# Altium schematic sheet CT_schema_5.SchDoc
size 430 x 429 mm
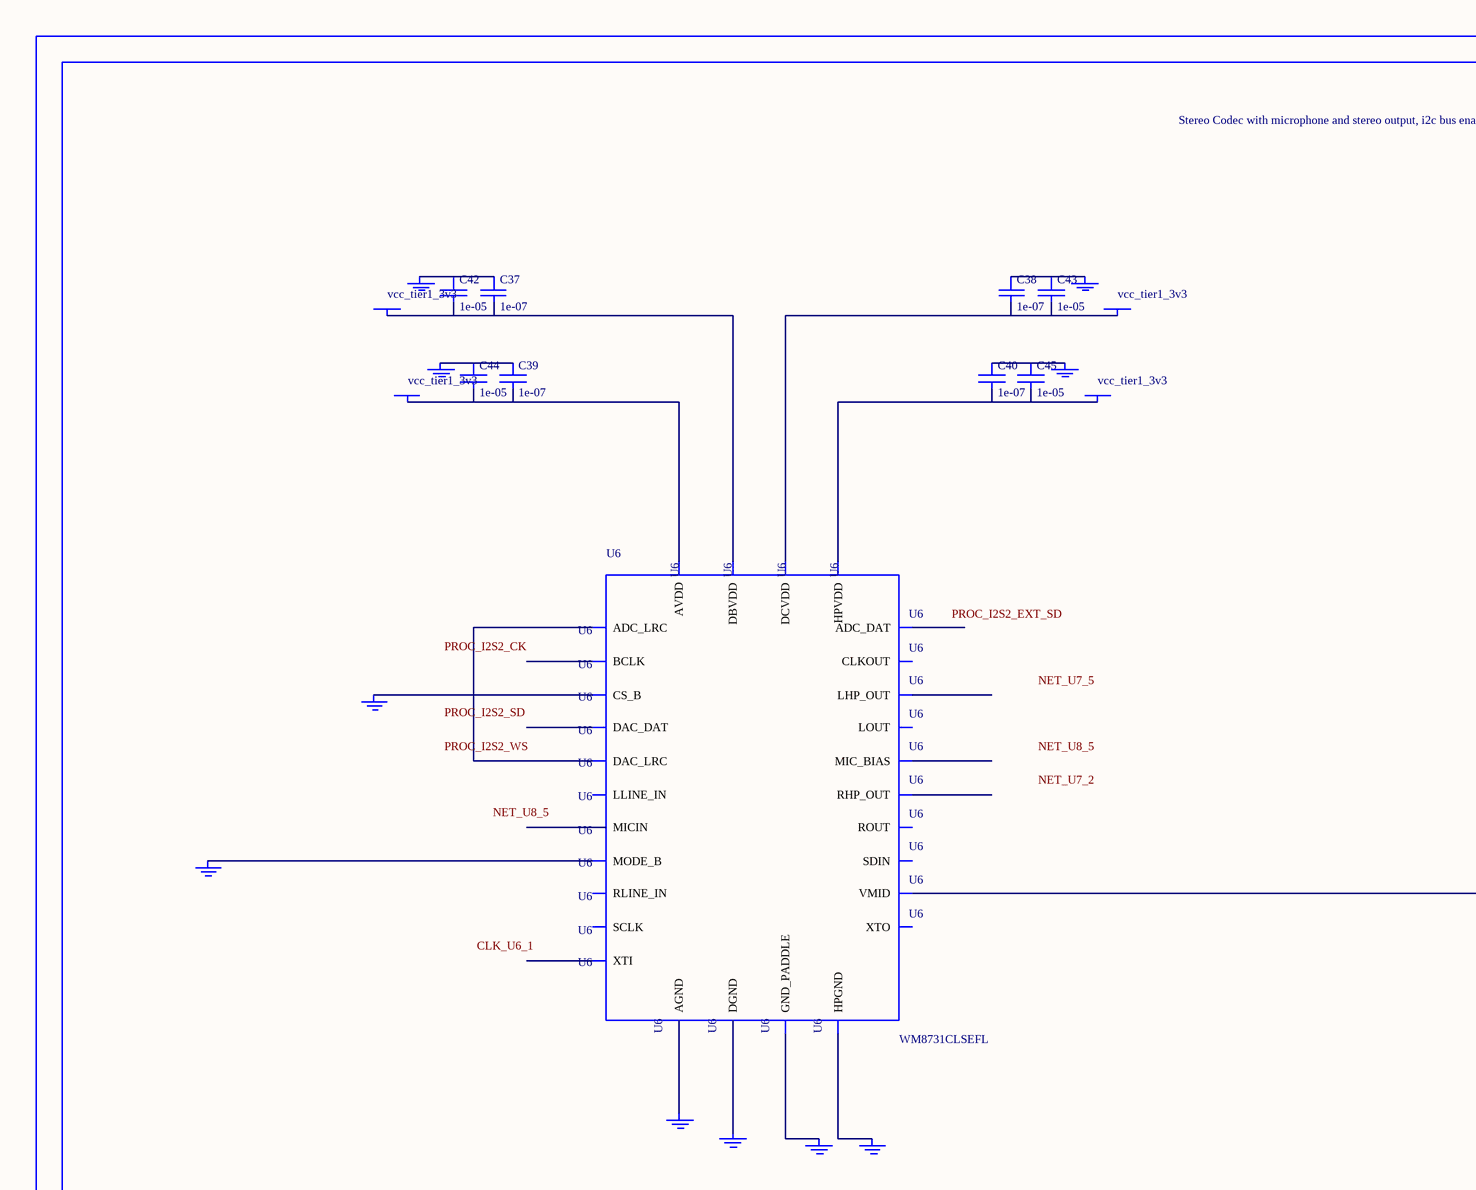
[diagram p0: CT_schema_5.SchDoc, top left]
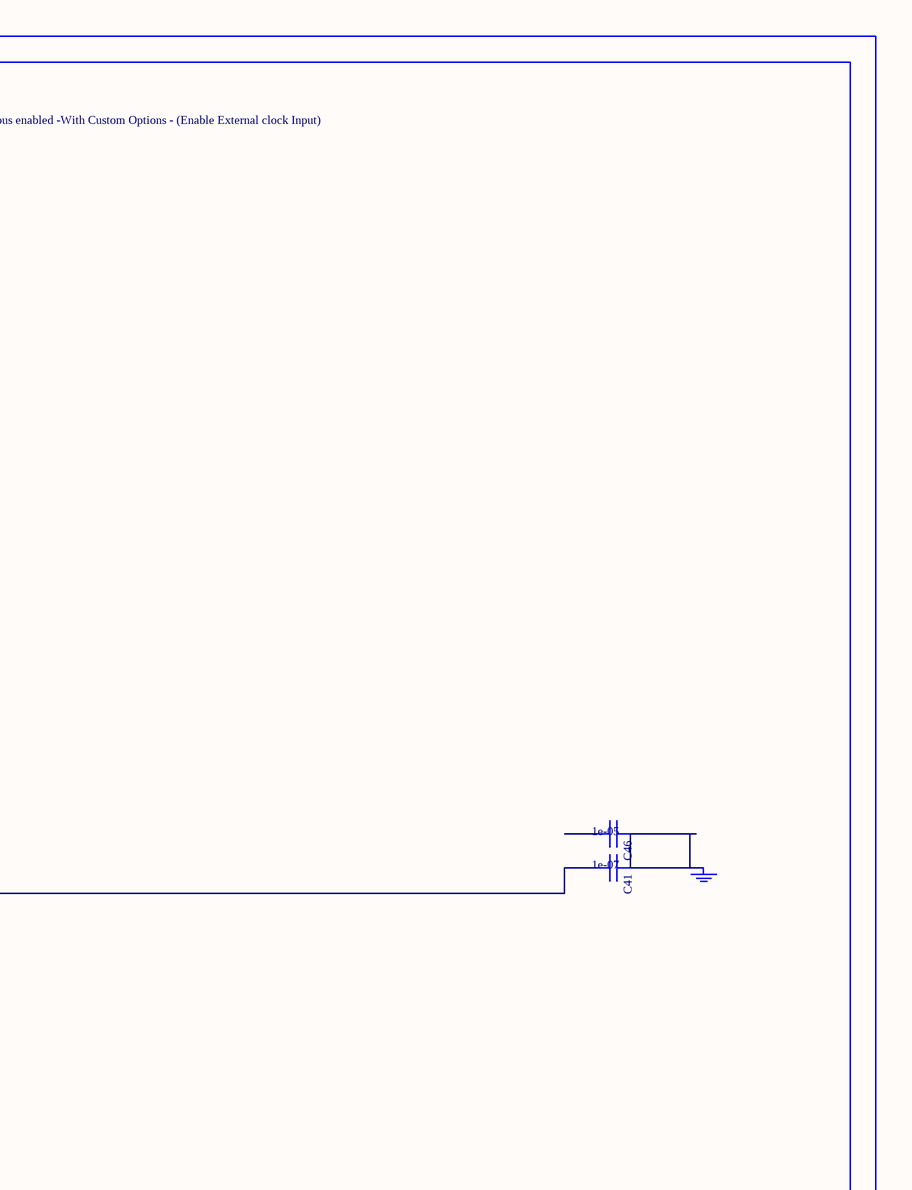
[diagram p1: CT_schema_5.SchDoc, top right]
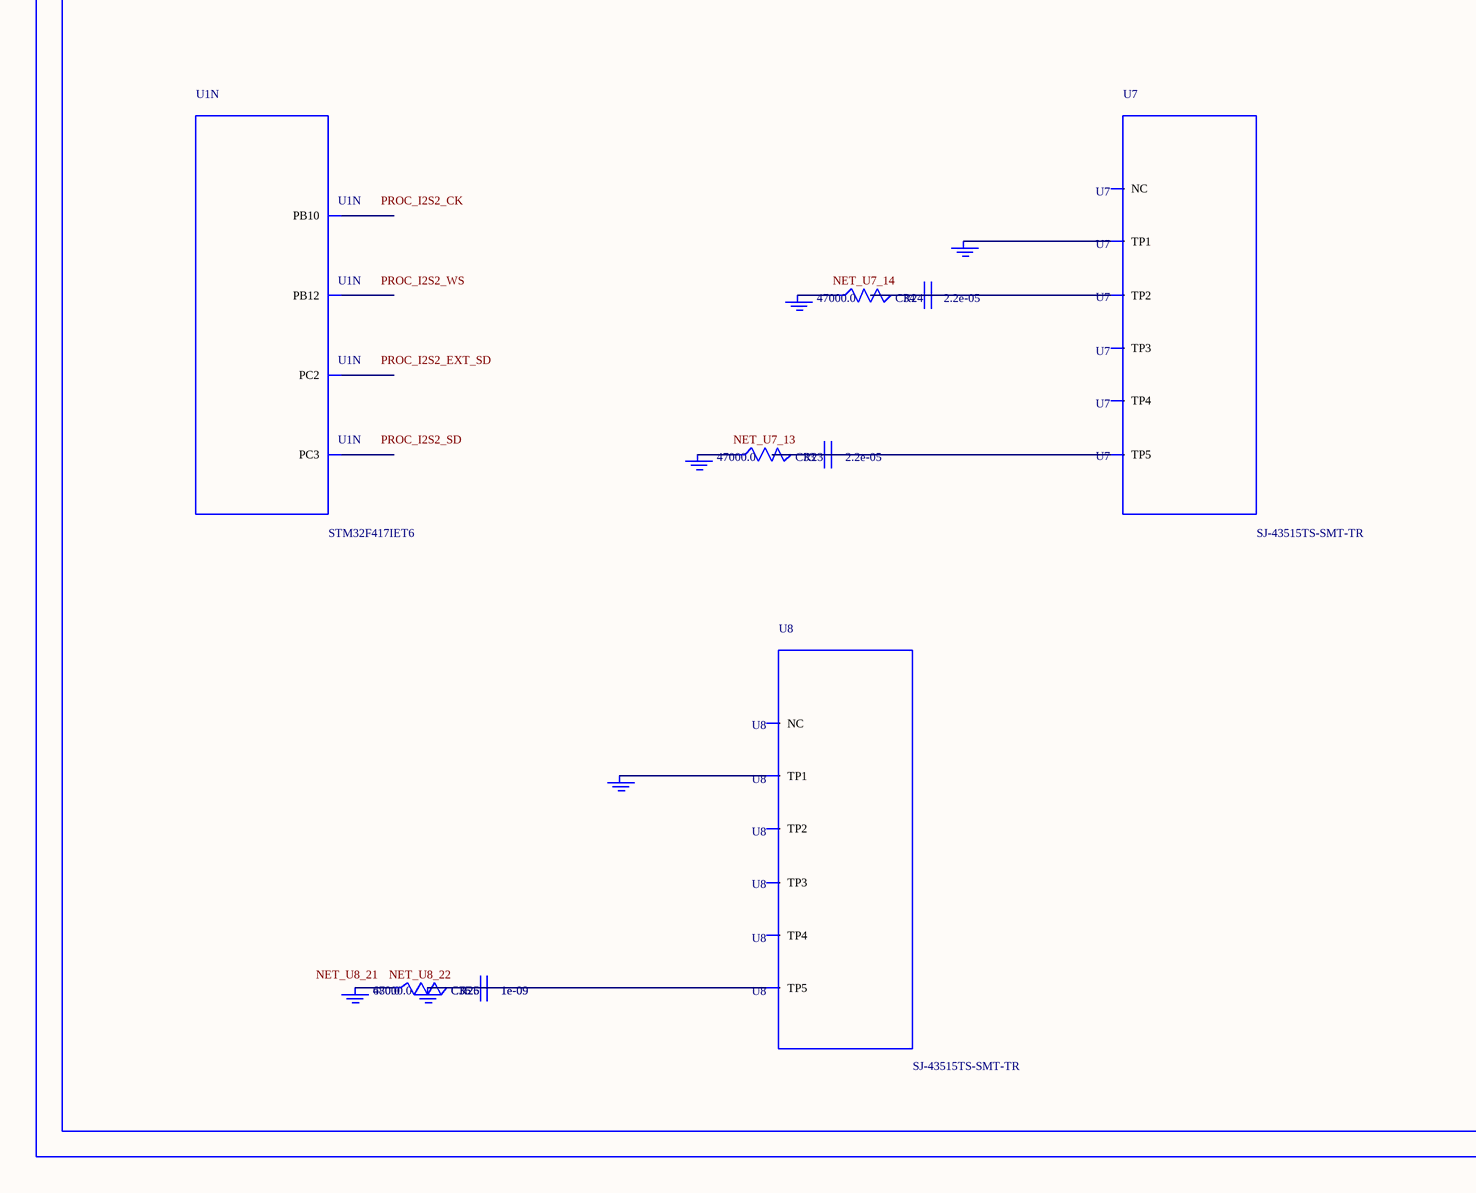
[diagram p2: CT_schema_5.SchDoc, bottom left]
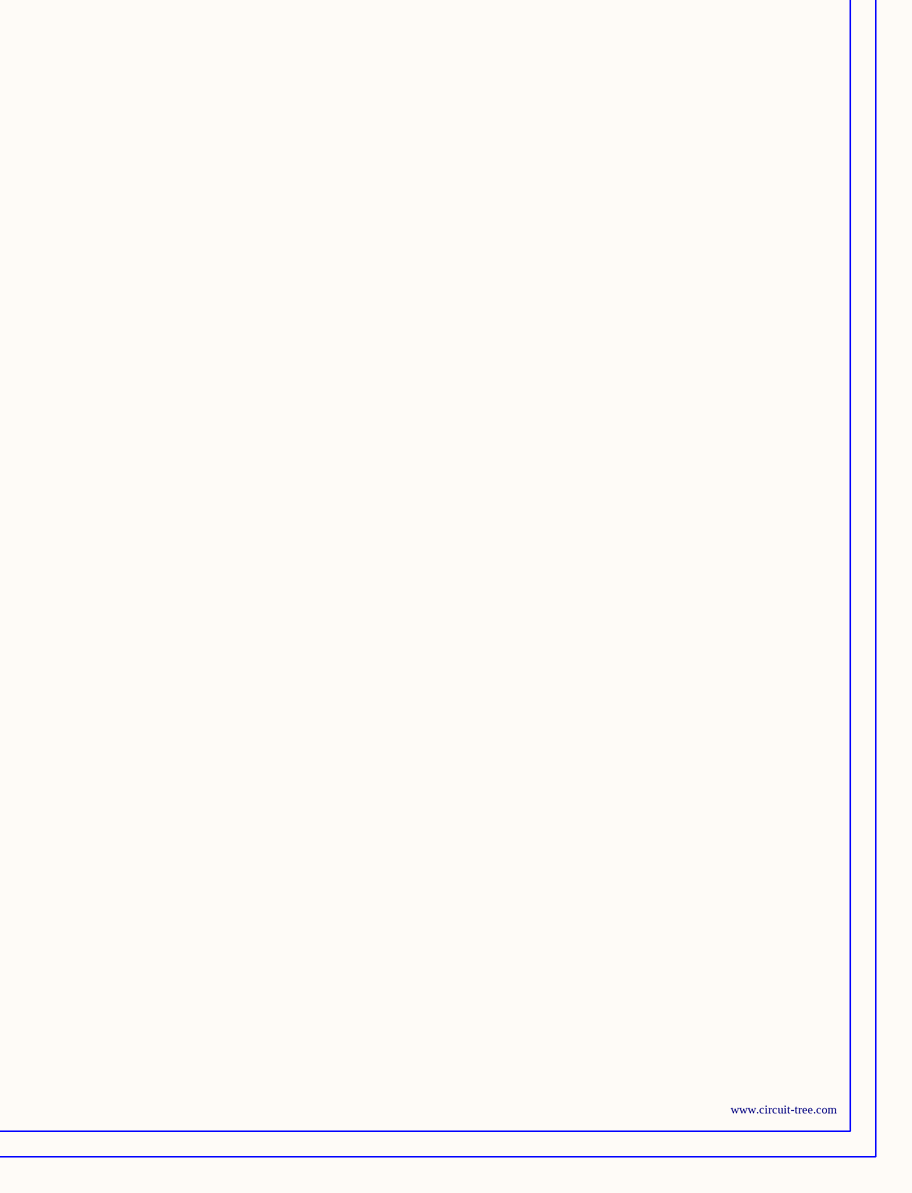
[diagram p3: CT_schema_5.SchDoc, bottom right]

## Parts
BORDER4  (no value)
C33  2.2e-05  [C1210]
C34  2.2e-05  [C1210]
C35  1e-09  [C0402]
C36  1e-09  [C0402]
C37  1e-07  [C0402]
C38  1e-07  [C0402]
C39  1e-07  [C0402]
C40  1e-07  [C0402]
C41  1e-07  [C0402]
C42  1e-05  [C0805]
C43  1e-05  [C0805]
C44  1e-05  [C0805]
C45  1e-05  [C0805]
C46  1e-05  [C0805]
GND_INSTANCE_4_0  (no value)
GND_INSTANCE_4_1  (no value)
GND_INSTANCE_4_2  (no value)
GND_INSTANCE_4_3  (no value)
GND_INSTANCE_4_4  (no value)
GND_INSTANCE_4_5  (no value)
GND_INSTANCE_4_6  (no value)
GND_INSTANCE_4_7  (no value)
GND_INSTANCE_4_8  (no value)
GND_INSTANCE_4_9  (no value)
GND_INSTANCE_4_10  (no value)
GND_INSTANCE_4_11  (no value)
GND_INSTANCE_4_12  (no value)
GND_INSTANCE_4_13  (no value)
GND_INSTANCE_4_14  (no value)
GND_INSTANCE_4_15  (no value)
GND_INSTANCE_4_16  (no value)
POWER_INSTANCE_4_0  vcc_tier1_3v3
POWER_INSTANCE_4_1  vcc_tier1_3v3
POWER_INSTANCE_4_2  vcc_tier1_3v3
POWER_INSTANCE_4_3  vcc_tier1_3v3
R23  47000.0  [R0603]
R24  47000.0  [R0603]
R25  47000.0  [R0603]
R26  680.0  [R0603]
U1  STM32F417IET6  [LQFP176]  (part N of 14)
U6  WM8731CLSEFL  [QFN-28]
U7  SJ-43515TS-SMT-TR  [SJ-43515TS-SMT-TR]
U8  SJ-43515TS-SMT-TR  [SJ-43515TS-SMT-TR]

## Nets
NetC33_1: C33.1 C33.2 R23.2 U7.5(TP5)
NetC34_1: C34.1 C34.2 R24.2 U7.2(TP2)
NetC35_1: C35.1 C35.2 C36.1 C36.2 GND_INSTANCE_4_16.0(GND) R25.2 R26.2 U8.5(TP5)
NetC37_1: C37.1 C42.1 GND_INSTANCE_4_1.0(GND)
NetC37_2: C37.2 C42.2 POWER_INSTANCE_4_1.0(PWR) U6.5(DBVDD)
NetC38_1: C38.1 C43.1 GND_INSTANCE_4_0.0(GND)
NetC38_2: C38.2 C43.2 POWER_INSTANCE_4_0.0(PWR) U6.3(DCVDD)
NetC39_1: C39.1 C44.1 GND_INSTANCE_4_4.0(GND)
NetC39_2: C39.2 C44.2 POWER_INSTANCE_4_3.0(PWR) U6.18(AVDD)
NetC40_1: C40.1 C45.1 GND_INSTANCE_4_2.0(GND)
NetC40_2: C40.2 C45.2 POWER_INSTANCE_4_2.0(PWR) U6.12(HPVDD)
NetC41_1: C41.1 C46.1 GND_INSTANCE_4_5.0(GND)
NetC41_2: C41.2 U6.20(VMID)
NetGND_INSTANCE_4_3_0: GND_INSTANCE_4_3.0(GND) U6.15(HPGND)
NetGND_INSTANCE_4_6_0: GND_INSTANCE_4_6.0(GND) U6.25(MODE_B)
NetGND_INSTANCE_4_7_0: GND_INSTANCE_4_7.0(GND) U6.26(CS_B)
NetGND_INSTANCE_4_8_0: GND_INSTANCE_4_8.0(GND) U6.29(GND_PADDLE)
NetGND_INSTANCE_4_9_0: GND_INSTANCE_4_9.0(GND) U6.4(DGND)
NetGND_INSTANCE_4_10_0: GND_INSTANCE_4_10.0(GND) U6.19(AGND)
NetGND_INSTANCE_4_11_0: GND_INSTANCE_4_11.0(GND) U7.1(TP1)
NetGND_INSTANCE_4_12_0: GND_INSTANCE_4_12.0(GND) R24.1
NetGND_INSTANCE_4_13_0: GND_INSTANCE_4_13.0(GND) R23.1
NetGND_INSTANCE_4_14_0: GND_INSTANCE_4_14.0(GND) U8.1(TP1)
NetGND_INSTANCE_4_15_0: GND_INSTANCE_4_15.0(GND) R25.1 R26.1
NetU6_9: U6.9(DAC_LRC) U6.11(ADC_LRC)

Not connected (* = marked no-connect by the designer): C46 2; U1 34(PC2) 35(PC3) 79(PB10) 92(PB12); U6 1(XTI) 2(XTO) 6(CLKOUT) 7(BCLK) 8(DAC_DAT) 10(ADC_DAT) 13(LHP_OUT) 14(RHP_OUT) 16(LOUT) 17(ROUT) 21(MIC_BIAS) 22(MICIN) 23(RLINE_IN) 24(LLINE_IN) 27(SDIN) 28(SCLK); U7 3(TP3) 4(TP4) 6(NC); U8 2(TP2) 3(TP3) 4(TP4) 6(NC)

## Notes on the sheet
- Labels drawn without touching a wire or pin: CLK_U6_1, NET_U7_2, NET_U7_5, NET_U7_13, NET_U7_14, NET_U8_5, NET_U8_21, NET_U8_22, PROC_I2S2_CK, PROC_I2S2_EXT_SD, PROC_I2S2_SD, PROC_I2S2_WS

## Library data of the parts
BORDER4 = BORDER_PAGE4
C33 C34 = C1210C224K5RACTU
C35 C36 = C0402C102K3RAC
C37-C41 = C0402C104K3RACTU
C42-C46 = C0805C106K8RACTU
GND_INSTANCE_4_0-GND_INSTANCE_4_16 = GND
POWER_INSTANCE_4_0-POWER_INSTANCE_4_3 = PWR
R23-R25 = RC0603JR-0747KL
R26 = RC0603JR-07680RL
